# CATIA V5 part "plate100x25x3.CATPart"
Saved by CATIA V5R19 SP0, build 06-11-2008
Part number: plate100x25x3
Bounding box of the stored display mesh (mm): x -100 to 0, y 0 to 3, z 0 to 25
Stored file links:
  D:\AUTO BATCH (BHEL)\Hexagonal Dome\plate100x25x3.CATPart
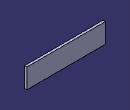
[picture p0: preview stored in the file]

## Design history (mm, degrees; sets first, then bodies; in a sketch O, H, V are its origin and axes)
SheetMetalParameters1: BendRadius 3, ReliefAxialLength 2, ReliefRadialLength 1, MinimumBendRadius 0, Thickness 3, KFactor 0.325257 {= log(min(100,max(20*SheetMetalParameters1.BendRadius,SheetMetalParameters1.Thickness)/SheetMetalParameters1.Thickness))/log(100)/2}
Body1 (main body)
  Sketch1 on zx-plane, origin (0, 0, 0), H (-1, 0, 0), V (0, 0, 1)
    line L1 (0, 0) -> (100, 0)
    line L2 (100, 0) -> (100, 25)
    line L3 (100, 25) -> (0, 25)
    line L4 (0, 25) -> (0, 0)
    length L1 = 100
    length L2 = 25
    horizontal: L1 H, L3 H
    vertical: L2 V, L4 V
  Wall1: Thickness 3, Profile Sketch1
